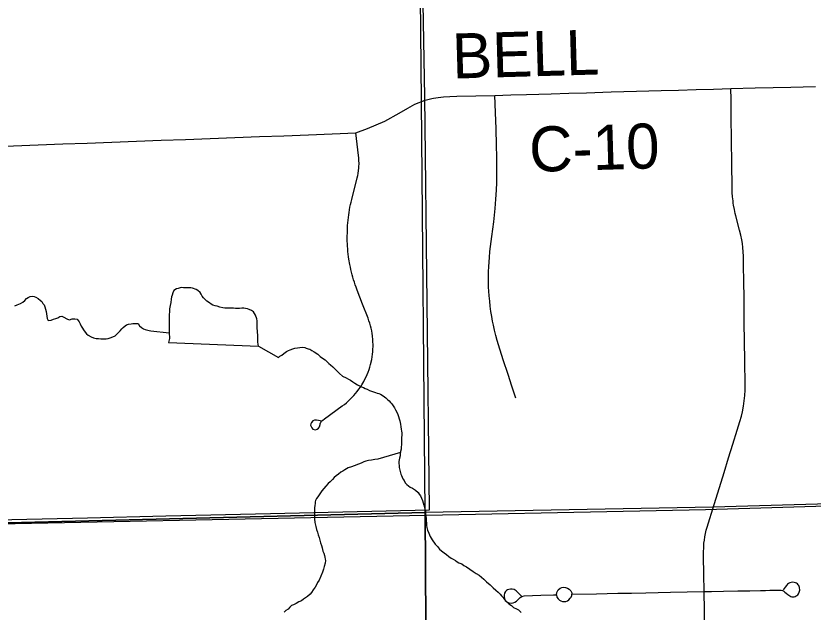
# Model space of a CAD drawing. Extents: x 103424 to 286016, y 38711 to 110967.
# Drawn here: x 117188 to 122536, y 42876 to 46874 of the extents above; entities that cross this region are included whole.
import ezdxf

# ---------------------------------------------------------------- set-up
doc = ezdxf.new("R2010")
doc.units = 0
for name, color, linetype in [('GM_X_City_Street', 7, 'Continuous'), ('GM_X_Corporation', 7, 'Continuous'), ('GM_X_County_Road', 7, 'Continuous'), ('GM_X_County_Road_Text', 7, 'Continuous'), ('GM_X_Minor_Lake', 7, 'Continuous'), ('GM_X_Minor_River', 7, 'Continuous'), ('GM_X_Rail_Line', 7, 'Continuous'), ('GM_X_Township_Road', 7, 'Continuous')]:
    doc.layers.add(name, color=color, linetype=linetype)

msp = doc.modelspace()

# ---------------------------------------------------------------- linework, layer by layer
at = {"layer": 'GM_X_City_Street'}
msp.add_lwpolyline([(119231.8, 44157.9), (119204.1, 44163.8), (119191, 44162.5), (119179.3, 44157.5), (119170.9, 44146.5), (119166.7, 44139), (119165, 44129.7), (119167.9, 44119.6), (119173.4, 44110.8), (119180.2, 44103.3), (119189.8, 44099.5), (119198.1, 44098.8), (119209.1, 44102.8), (119218.4, 44109.5), (119224.2, 44118.4), (119229.3, 44133.1), (119230.2, 44138.9), (119233.9, 44150.3), (119241.4, 44158.7), (119246.2, 44164.1), (119258.3, 44173), (119377.6, 44258.5), (119391.7, 44269.1), (119405.3, 44280.1), (119418.4, 44291.7), (119431.3, 44303.7), (119443.6, 44316.2), (119455.7, 44329.1), (119467.3, 44342.4), (119478.1, 44356), (119488.7, 44370.1), (119498.8, 44384.5), (119508.3, 44399.2), (119521.7, 44422), (119530, 44437.5), (119537.6, 44453.3), (119544.6, 44469.4), (119551.2, 44485.7), (119557.2, 44502.2), (119562.5, 44518.9), (119567.5, 44535.8), (119575.4, 44570.1), (119578.4, 44587.4), (119580.7, 44604.8), (119582.4, 44622.2), (119583.7, 44639.8), (119584.2, 44657.4), (119583, 44701.3), (119580.5, 44727.6), (119578, 44744.9), (119575, 44762.2), (119571.2, 44779.4), (119566.9, 44796.5), (119562.1, 44813.3), (119556.6, 44830), (119550.6, 44846.5), (119514.2, 44940.4), (119477.9, 45034.4), (119470.4, 45054.7), (119464.6, 45071.2), (119459.1, 45087.9), (119453.8, 45104.7), (119448.8, 45121.5), (119444.2, 45138.5), (119439.7, 45155.5), (119435.7, 45172.6), (119431.9, 45189.8), (119428.4, 45206.9), (119422.4, 45241.6), (119419.9, 45259), (119417.6, 45276.4), (119415.6, 45293.9), (119414.1, 45311.4), (119412.6, 45328.9), (119411.6, 45346.4), (119410.9, 45364), (119411.9, 45451.8), (119412.9, 45469.4), (119414.5, 45486.9), (119416.2, 45504.4), (119418.3, 45521.8), (119420.5, 45539.2), (119423, 45556.6), (119426.1, 45573.9), (119429.3, 45591.2), (119432.9, 45608.4), (119436.7, 45625.5), (119441, 45642.6), (119477.8, 45789.1), (119481, 45803.2), (119483.8, 45817.2), (119486.9, 45838.2), (119488.4, 45852.3), (119489.4, 45866.5), (119489.9, 45880.7), (119489.4, 45909), (119488.4, 45923.2), (119486.9, 45937.3), (119468.9, 46088.8)], dxfattribs=at)
at = {"layer": 'GM_X_Corporation'}
for points in [[(103423.7, 70904.9), (103423.7, 43132.7), (108691.3, 43264.4), (116952, 43470.9), (119934.2, 43543), (119908.2, 46302.1), (119859.8, 51426.6), (119800.4, 57496.9), (119747.3, 63220.6), (119711.4, 67089.1)], [(149451.3, 44180.8), (147524, 44122.7), (147511.7, 44122.4), (144100.1, 44042.4), (133604.6, 43873.3), (130307.3, 43800.5), (126993.8, 43728), (121865.1, 43580.2), (119934.2, 43543), (119908.2, 46302.1), (119859.8, 51426.6), (119800.4, 57496.9), (119747.3, 63220.6), (119711.4, 67089.1)], [(116953.7, 43492.4), (117668.8, 43508.8), (118194.1, 43520.8), (118895.2, 43536.8), (119961.9, 43561.2), (119932.5, 46334.5), (119886.4, 48829.9), (118136.2, 48708), (117498.8, 48671.3), (116838, 48636.4)]]:
    msp.add_lwpolyline(points, dxfattribs=at)
for points in [[(119963.5, 38711.2), (149532.9, 38711.2), (149528, 39851), (149476.1, 42604.7), (149451.3, 44180.8), (147524, 44122.7), (147511.7, 44122.4), (144100.1, 44042.4), (133604.6, 43873.3), (130307.3, 43800.5), (126993.8, 43728), (121865.1, 43580.2), (119934.2, 43543)], [(103423.7, 43132.7), (103423.7, 38711.2), (119963.5, 38711.2), (119934.2, 43543), (116952, 43470.9), (108691.3, 43264.4)]]:
    msp.add_lwpolyline(points, close=True, dxfattribs=at)
at = {"layer": 'GM_X_County_Road'}
for points in [[(119978.3, 46319.5), (119989.3, 46322), (120020.7, 46327.1), (120057.6, 46330.6), (120098.8, 46333.4), (120146.7, 46335.2), (120274.5, 46338), (120402.3, 46340.9), (120508.3, 46344), (120614.2, 46347.1), (120779.2, 46352), (120898.2, 46355.5), (121017.3, 46359), (121182.3, 46363.8), (121266.8, 46366.3), (121351.3, 46368.8), (121516.3, 46373.3), (121634, 46376.5), (121751.6, 46379.7), (121867.7, 46382.9), (121983.7, 46386.1), (122148.7, 46390.6), (122268, 46393.8), (122387.4, 46397), (122552.4, 46400.9)], [(119934.2, 46308.9), (119961.7, 46315.8), (119978.3, 46319.5)], [(116827.1, 45995.8), (116992.1, 45999.1), (117082.1, 46000.9), (117172.1, 46002.8), (117337.1, 46009), (117502, 46015.1), (117666.9, 46021.3), (117831.9, 46027.5), (117996.8, 46033.7), (118161.7, 46039.8), (118326.7, 46046), (118491.6, 46052.2), (118656.5, 46058.3), (118821.5, 46064.5), (118986.4, 46070.7), (119151.3, 46076.9), (119310.1, 46082.8), (119468.9, 46088.8), (119547.2, 46118.9), (119662.4, 46168), (119759.3, 46221.7), (119816.6, 46254.5), (119865.2, 46281.3), (119934.2, 46308.9)]]:
    msp.add_lwpolyline(points, dxfattribs=at)
at = {"layer": 'GM_X_Minor_Lake'}
msp.add_line((118211.1, 44683.7), (118816.1, 44658.6), dxfattribs=at)
msp.add_lwpolyline([(118816.1, 44658.6), (118811.4, 44687), (118811.4, 44735.4), (118809.4, 44751.5), (118809.4, 44763.6), (118807.4, 44775.7), (118807.5, 44801.9), (118805.5, 44816), (118805.5, 44830.1), (118803.5, 44842.2), (118795.4, 44866.4), (118789.4, 44878.5), (118781.4, 44890.6), (118769.3, 44898.6), (118753.2, 44904.7), (118741.2, 44908.7), (118729.1, 44910.8), (118717.1, 44914.8), (118703, 44914.8), (118688.9, 44912.8), (118660.7, 44912.8), (118646.7, 44914.8), (118590.3, 44914.8), (118576.3, 44916.9), (118556.2, 44920.9), (118538.1, 44926.9), (118524, 44929), (118509.9, 44935), (118497.9, 44941.1), (118485.8, 44949.1), (118469.7, 44961.2), (118457.7, 44971.3), (118445.6, 44983.4), (118437.6, 44995.5), (118431.5, 45007.6), (118423.5, 45019.7), (118409.4, 45031.8), (118397.4, 45039.9), (118373.2, 45047.9), (118361.2, 45049.9), (118325, 45050), (118312.9, 45050), (118300.8, 45052), (118288.8, 45050), (118276.7, 45045.9), (118264.6, 45043.9), (118246.5, 45031.8), (118240.5, 45017.7), (118236.4, 45001.6), (118232.4, 44989.5), (118230.4, 44975.4), (118226.3, 44951.2), (118222.3, 44933.1), (118218.2, 44908.9), (118218.2, 44886.8), (118216.2, 44874.7), (118216.1, 44737.6), (118218.1, 44723.5), (118218.1, 44711.4), (118211.1, 44683.7)], dxfattribs=at)
at = {"layer": 'GM_X_Minor_River'}
for points in [[(117181.5, 44929), (117195.5, 44937.3), (117217.6, 44945.7), (117233.6, 44954.1), (117247.5, 44964.4), (117259.4, 44978.8), (117269.4, 44985), (117283.4, 44991.3), (117297.5, 44993.5), (117309.6, 44991.7), (117321.8, 44987.9), (117336, 44980), (117352.4, 44966.2), (117362.6, 44958.2), (117368.9, 44946.2), (117377.1, 44936.3), (117381.4, 44922.2), (117385.7, 44908.1), (117390, 44892), (117392.3, 44875.9), (117394.6, 44859.8), (117396.8, 44845.7), (117403.1, 44831.6), (117425.3, 44834), (117439.3, 44840.3), (117455.3, 44844.6), (117469.4, 44848.9), (117483.4, 44857.2), (117495.5, 44859.4), (117505.6, 44855.5), (117534.1, 44839.8), (117546.3, 44836), (117564.3, 44842.4), (117582.5, 44842.7), (117598.7, 44840.9), (117613.1, 44823), (117619.4, 44808.9), (117625.7, 44792.9), (117634, 44780.9), (117640.3, 44768.9), (117652.6, 44752.9), (117660.9, 44740.9), (117673.1, 44733), (117693.5, 44721.3), (117707.7, 44715.4), (117726, 44711.7), (117742.1, 44709.9), (117758.3, 44708.2), (117776.5, 44708.5), (117792.6, 44708.8), (117806.7, 44711), (117820.7, 44715.3), (117838.8, 44721.6), (117852.8, 44727.9), (117862.7, 44738.2), (117874.7, 44748.5), (117886.5, 44762.8), (117898.4, 44775.1), (117908.4, 44783.4), (117920.3, 44795.7), (117930.3, 44801.9), (117942.3, 44806.2), (117960.4, 44808.5), (117972.5, 44810.7)], [(117972.5, 44810.7), (117986.6, 44810.9), (117996.7, 44811.1), (118008.8, 44811.3), (118017.2, 44795.3), (118029.5, 44783.4), (118043.7, 44775.5), (118053.9, 44771.6), (118072.1, 44765.9), (118082.3, 44764), (118092.4, 44762.2), (118216.1, 44748.5)], [(118816.1, 44658.6), (118948.9, 44584.3), (118958.9, 44592.6), (118970.9, 44598.8), (118984.8, 44611.2), (119002.8, 44623.6), (119016.8, 44629.9), (119028.8, 44634.1), (119044.8, 44642.5), (119058.9, 44646.8), (119111.3, 44651.7), (119125.4, 44649.9), (119135.6, 44646), (119147.7, 44642.2), (119159.9, 44638.3), (119172.2, 44630.4), (119188.5, 44620.6), (119212.9, 44604.9), (119229.3, 44591), (119245.7, 44579.1), (119262, 44567.3), (119274.3, 44555.4), (119286.6, 44543.4), (119298.9, 44533.5), (119313.2, 44521.7), (119325.5, 44509.7), (119341.9, 44493.8), (119358.4, 44475.9), (119378.9, 44458.1), (119403.3, 44446.4), (119419.5, 44438.6), (119433.8, 44430.7), (119448.1, 44420.8), (119462.4, 44411), (119478.7, 44401.1), (119493, 44393.3), (119507.2, 44387.5), (119519.4, 44381.6), (119531.6, 44375.8), (119543.8, 44369.9), (119560.1, 44362.1), (119574.3, 44358.3), (119586.5, 44352.4), (119600.6, 44348.6), (119610.8, 44344.7), (119623, 44340.9), (119633.1, 44337), (119651.5, 44325.2), (119669.8, 44313.4), (119680.2, 44301.4), (119692.4, 44293.6), (119700.7, 44281.6), (119710.9, 44271.6), (119719.2, 44259.7), (119727.5, 44245.7), (119735.8, 44231.6), (119744.1, 44217.6), (119750.4, 44201.6), (119763.2, 44159.4), (119767.7, 44137.2), (119770, 44119.1), (119772.3, 44103), (119774.5, 44088.9), (119776.7, 44078.8), (119777, 44062.6), (119775.2, 44046.4), (119775.4, 44036.3), (119774, 44000), (119772.3, 43981.7), (119772.5, 43967.6), (119768.7, 43953.4), (119767, 43935.2), (119765.2, 43923), (119761.4, 43908.8), (119759.6, 43896.7), (119757.8, 43886.6), (119758, 43872.4), (119758.2, 43858.3), (119758.4, 43846.2), (119760.6, 43836.1), (119771.3, 43801.9), (119775.5, 43791.9), (119779.7, 43781.9), (119783.9, 43769.8), (119792.2, 43757.8), (119800.5, 43743.8), (119810.8, 43731.9), (119821, 43721.9), (119833.3, 43714.1), (119849.6, 43706.3), (119867.9, 43694.4), (119886.4, 43678.6), (119894.6, 43666.6), (119902.9, 43654.6), (119909.2, 43640.6), (119915.5, 43624.5)], [(119768, 43945.2), (119616.2, 43902.4), (119596.1, 43900.1), (119574, 43895.7), (119553.8, 43893.3), (119535.7, 43889), (119521.7, 43882.7), (119503.7, 43874.3), (119439.5, 43851), (119417.5, 43842.6), (119405.5, 43836.3), (119395.5, 43830.1), (119381.5, 43821.8), (119367.5, 43813.5), (119351.6, 43801.1), (119337.6, 43788.7), (119323.7, 43778.4), (119311.8, 43764.1), (119295.9, 43749.7), (119282, 43737.3), (119268.2, 43720.9), (119254.3, 43704.5), (119240.5, 43688.1), (119230.6, 43675.9), (119222.7, 43661.6), (119212.9, 43649.3), (119205, 43637.1), (119197.1, 43624.8), (119195.3, 43614.7), (119195.4, 43604.6), (119193.7, 43590.4), (119191.9, 43576.2), (119192.1, 43564.1), (119190.3, 43547.9), (119190.7, 43527.7), (119191.1, 43501.5), (119193.5, 43477.3), (119200, 43451.1), (119204.4, 43431), (119210.8, 43412.9), (119215.1, 43394.8), (119221.5, 43376.7), (119227.8, 43358.6), (119232.2, 43340.5), (119238.5, 43322.5), (119242.8, 43306.4), (119247.2, 43284.2), (119253.5, 43270.2), (119257.8, 43256.1), (119260, 43244), (119262.2, 43231.9), (119264.4, 43221.9), (119262.7, 43203.7), (119257, 43181.4), (119251.3, 43163.1), (119245.5, 43144.8), (119222.3, 43089.9), (119212.4, 43075.6), (119204.6, 43059.3), (119194.8, 43043), (119183, 43024.6), (119171.2, 43008.2), (119161.3, 42995.9), (119143.4, 42981.5), (119131.4, 42971.2), (119117.4, 42962.9), (119103.5, 42952.6), (119085.5, 42944.2), (119067.5, 42933.8), (119049.5, 42925.4), (119037.4, 42921.2), (119025.5, 42908.9), (119013.6, 42896.6), (118999.7, 42886.2), (118987.7, 42875.9)], [(119915.5, 43624.5), (119919.8, 43608.4), (119924.1, 43592.3), (119928.4, 43576.2), (119932.6, 43566.2), (119934.9, 43552.1), (119937.1, 43538), (119937.4, 43519.8), (119939.7, 43503.7), (119940, 43487.5), (119942.3, 43473.4), (119942.5, 43457.3), (119944.8, 43443.2), (119949.1, 43425.1), (119957.5, 43405), (119968, 43383), (119980.5, 43360.9), (120001.2, 43331), (120017.6, 43315.1), (120029.9, 43299.1), (120044.3, 43287.2), (120060.7, 43273.4), (120077, 43261.5), (120093.3, 43249.7), (120107.7, 43237.8), (120121.9, 43229.9), (120136.2, 43222.1), (120148.4, 43214.2), (120160.7, 43206.3), (120178.9, 43198.6), (120193.2, 43188.7), (120211.6, 43178.9), (120256.5, 43149.3), (120276.9, 43135.5), (120295.2, 43123.7), (120311.6, 43109.8), (120328, 43095.9), (120344.4, 43080), (120371, 43058.3), (120389.5, 43038.4), (120407.9, 43022.5), (120424.3, 43008.6), (120436.6, 42996.7), (120446.9, 42984.8), (120457.1, 42974.8), (120465.4, 42960.8), (120479.8, 42946.9), (120496.2, 42931), (120512.6, 42919.2), (120526.9, 42907.3), (120547.2, 42897.5), (120559.4, 42891.7), (120577.9, 42873.8)]]:
    msp.add_lwpolyline(points, dxfattribs=at)
at = {"layer": 'GM_X_Rail_Line'}
msp.add_lwpolyline([(103423.7, 43097.6), (108679.4, 43247.4), (116958, 43465.4), (121815.2, 43564.4), (126929.9, 43718), (126994.3, 43782.4), (126944.8, 46442.1), (126989.3, 46496.6), (133017.7, 46606.6), (136395.4, 46646.5), (144375.8, 46798.7), (146504.9, 45437.9), (151249.2, 45325.6)], dxfattribs=at)
at = {"layer": 'GM_X_Township_Road'}
for points in [[(121873.9, 43598.4), (121908.5, 43712.1), (121939.2, 43811.1), (121969.9, 43910.1), (121998.7, 44003), (122027.5, 44095.9), (122045.8, 44153.5), (122055.6, 44190), (122062.2, 44218), (122069.8, 44255.9), (122075.1, 44292.3), (122079.1, 44328.4), (122080.9, 44363.5), (122081.4, 44397.8), (122079, 44562.8), (122077.1, 44690.8), (122075.2, 44818.9), (122073.2, 44984), (122071.9, 45092.2), (122070.6, 45200.5), (122070, 45233.1), (122069.1, 45261.7), (122067.7, 45291.6), (122065.1, 45321.4), (122062.4, 45346.7), (122058.4, 45371.6), (122052.2, 45403.2), (122043.9, 45436.6), (122018, 45534.1), (122014.4, 45548.1), (122011.4, 45562.2), (122008.4, 45576.3), (122003.4, 45604.6), (122001.1, 45618.8), (121999.4, 45633), (121997.6, 45647.4), (121996.1, 45661.7), (121994.1, 45690.4), (121993.4, 45704.7), (121992.9, 45726.3), (121991.1, 45883.2), (121989.3, 46039.8), (121987.5, 46196.3), (121986.2, 46313.7), (121983.7, 46386.1)], [(120541.8, 44311.3), (120516, 44390.2), (120490.2, 44469.2), (120458.2, 44568.5), (120426.1, 44667.9), (120417.4, 44696.7), (120408, 44731.6), (120399.4, 44765.6), (120391.5, 44799.7), (120385.7, 44827.4), (120380.4, 44857.6), (120375.3, 44891.8), (120370.6, 44926.9), (120366.6, 44961.3), (120363.3, 44995.9), (120360.9, 45027.2), (120359.4, 45054.8), (120358.1, 45087.4), (120358.7, 45160.1), (120359.9, 45191.4), (120362.2, 45224), (120364.6, 45254.1), (120368.7, 45294.1), (120381.2, 45394), (120393.8, 45493.9), (120403.8, 45583.4), (120408.8, 45644.8), (120411.9, 45704.9), (120414.4, 45755.7), (120415.7, 45812), (120415, 45926), (120413.2, 46007.4), (120409.6, 46116.4), (120406.1, 46225.4), (120402.3, 46340.9)], [(121805.2, 43013.5), (121803.5, 43131), (121801.7, 43248.4), (121801.3, 43270.6), (121802.8, 43315.1), (121804.6, 43337.2), (121807.3, 43359.3), (121810.9, 43381.3), (121815.2, 43403.1), (121820.2, 43424.7), (121826, 43446.2), (121873.9, 43598.4)], [(121805.2, 43013.5), (121855.9, 43014.1), (121936, 43015.8), (122032.8, 43017.8), (122111.8, 43019.5), (122183.7, 43021), (122218.3, 43021.7), (122246.5, 43022.3), (122314.5, 43023.8), (122322.8, 43022.9), (122330.9, 43020.6), (122340, 43016.3), (122347, 43010.4), (122356.1, 43002.7), (122367.7, 42993), (122380.4, 42984.5), (122388.2, 42980.8), (122394.8, 42978.7), (122402.1, 42978.3), (122409.8, 42979.2), (122416.5, 42981.1), (122422.7, 42984), (122428.5, 42987.4), (122433.3, 42991.7), (122438.6, 42998.5), (122441.5, 43003.8), (122445.3, 43015.3), (122447.3, 43024), (122445.8, 43041.7), (122443.3, 43047.5), (122440.1, 43053.3), (122436.2, 43059.3), (122431.9, 43064.9), (122426.1, 43069.2), (122419.4, 43072.6), (122409.8, 43075.5), (122398.2, 43076.4), (122388.6, 43075), (122380.4, 43072.1), (122372.7, 43068.2), (122366, 43062.4), (122358.3, 43054.8), (122349.1, 43044.2), (122336.6, 43025.4)], [(120580.7, 42982.3), (120557.2, 43005.4), (120543.8, 43018.1), (120531.1, 43026.5), (120518, 43030), (120506.5, 43030.9), (120496.2, 43028.4), (120487, 43025.3), (120479.9, 43020.5), (120472, 43013.4), (120466.8, 43002.7), (120464, 42990.4), (120462.8, 42977.7), (120465.6, 42966.2), (120471.2, 42954.3), (120481.1, 42944.8), (120494.2, 42938), (120511.2, 42935.6), (120525.1, 42938.4), (120535.8, 42943.2), (120545.7, 42949.9), (120562, 42965.7), (120571.1, 42973.7), (120583.4, 42980.3), (120598, 42985.3), (120710.7, 42989), (120793.8, 42991.7), (120815.3, 42991.9)], [(120815.3, 42991.9), (120816.5, 43007), (120825.5, 43024.3), (120838.8, 43037.4), (120850.5, 43041.6), (120863.5, 43042.7), (120876.3, 43041), (120888.5, 43036.2), (120899.8, 43028.7), (120910.8, 43018), (120917.1, 43005.8), (120918.8, 42996.1)], [(121227.6, 43002.2), (121248.9, 43002.6), (121318.1, 43004)], [(121318.1, 43004), (121413.9, 43005.8), (121578.9, 43009.1), (121692.1, 43011.3), (121805.2, 43013.5)], [(121827.2, 41996.3), (121823.7, 42161.3), (121820.9, 42295.2), (121818.1, 42429.1), (121814.5, 42594.1), (121810.8, 42759.2), (121808, 42886.4), (121805.2, 43013.5)], [(120815.3, 42991.9), (120818, 42976.7), (120825.5, 42964.2), (120834.9, 42956.2), (120844.1, 42950.6), (120854.2, 42947.3), (120866.2, 42946.2), (120878, 42947.3), (120888.7, 42951.8), (120898.6, 42959.2), (120907.5, 42968.5), (120913.1, 42977.1), (120917, 42987.2), (120918.8, 42996.1)], [(120918.8, 42996.1), (121083.8, 42999.4), (121227.6, 43002.2)]]:
    msp.add_lwpolyline(points, dxfattribs=at)

# ---------------------------------------------------------------- texts
at = {"layer": 'GM_X_County_Road_Text'}
for s, rotation, p in [('BELL', 1.641, (120118.6, 46453.3)), ('C-10', 1.713, (120635.8, 45827.2))]:
    msp.add_text(s, height=301.87, rotation=rotation, dxfattribs=at).set_placement(p)

doc.saveas('drawing.dxf')
